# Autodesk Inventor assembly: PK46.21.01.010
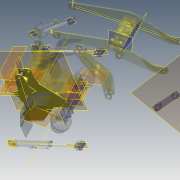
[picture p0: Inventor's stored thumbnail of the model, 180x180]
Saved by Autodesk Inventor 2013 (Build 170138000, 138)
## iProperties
Created: 2005-04
Part Number: PK46.21.01.010
Document SubType Name: Assembly
Designer: salex
Manufacturer: Standard
Standards Organization: Custom
Author: salex
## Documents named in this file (9)
- C:\Product Design Suite 2013\Data\Assy, Chassis, Front\PK46.21.01.010.iam
- C:\Product Design Suite 2013\Data\Assy, Chassis, Front\PK46.21.01.001.ipt
- C:\Product Design Suite 2013\Data\Assy, Chassis, Front\PK46.21.01.002.ipt
- C:\Product Design Suite 2013\Data\Assy, Chassis, Front\PK46.21.01.003.ipt
- C:\Product Design Suite 2013\Data\Assy, Chassis, Front\PK46.21.01.004.ipt
- C:\Product Design Suite 2013\Data\Assy, Chassis, Front\PK46.21.01.005.ipt
- C:\Product Design Suite 2013\Data\Assy, Chassis, Front\PK46.80.00.015.ipt
- C:\Product Design Suite 2013\Data\Assy, Chassis, Front\PK46.21.01.033.ipt
- C:\Product Design Suite 2013\Data\Assy, Chassis, Front\PK46.21.01.034.ipt
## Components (10 placed, 8 different names)
1. PK46.21.01.002:1 — Mate:1, Mate:3, Mate:4, Mate:5, Insert:1, Insert:4, Mate:17, Angle:1, Mate:16, Insert:8
2. PK46.21.01.001:1 — Mate:2, Mate:3, Mate:4, Insert:2, Insert:3
3. PK46.21.01.003:1 — Insert:2
4. PK46.21.01.003:2 — Insert:1
5. PK46.21.01.004:1 — Mate:5, Mate:15
6. PK46.21.01.005:1 — Mate:1, Mate:2, Mate:15
7. PK46.80.00.015:1 — Insert:3, Flush:2
8. PK46.80.00.015:2 — Insert:4, Flush:3, Mate:18
9. PK46.21.01.034:1 — Insert:8
10. PK46.21.01.033:1 — Mate:17, Angle:1, Mate:16
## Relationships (17: Mate 9, Insert 5, Flush 2, Angle 1)
- Mate:1: PK46.21.01.002:1 ↔ PK46.21.01.005:1
- Mate:2: PK46.21.01.001:1 ↔ PK46.21.01.005:1
- Mate:3: PK46.21.01.002:1 ↔ PK46.21.01.001:1
- Mate:4: PK46.21.01.002:1 ↔ PK46.21.01.001:1
- Mate:5: PK46.21.01.002:1 ↔ PK46.21.01.004:1
- Insert:1: PK46.21.01.002:1 ↔ PK46.21.01.003:2
- Insert:2: PK46.21.01.001:1 ↔ PK46.21.01.003:1
- Insert:3: PK46.21.01.001:1 ↔ PK46.80.00.015:1
- Insert:4: PK46.21.01.002:1 ↔ PK46.80.00.015:2
- Flush:2: PK46.80.00.015:1
- Mate:15: PK46.21.01.004:1 ↔ PK46.21.01.005:1
- Mate:17: PK46.21.01.002:1 ↔ PK46.21.01.033:1
- Angle:1: PK46.21.01.002:1 ↔ PK46.21.01.033:1
- Mate:16: PK46.21.01.002:1 ↔ PK46.21.01.033:1
- Insert:8: PK46.21.01.002:1 ↔ PK46.21.01.034:1
- Flush:3: PK46.80.00.015:2
- Mate:18: PK46.80.00.015:2
